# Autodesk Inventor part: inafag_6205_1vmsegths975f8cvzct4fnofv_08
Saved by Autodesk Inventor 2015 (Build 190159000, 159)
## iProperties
Company: TraceParts S.A.
Created: 2012-12
Part Number: inafag_6205_1vmsegths975f8cvzct4fnofv_08
Checked By: TraceParts S.A.
Catalog Web Link: www.traceparts.com
Document SubType Name: Modeling
Designer: TraceParts
Material: Generic
Density: 1 g/cm^3
Appearance: Default
Author: TraceParts
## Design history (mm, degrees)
feature "inafag_6205_1vmsegths975f8cvzct4fnofv"
body "Solid1"
